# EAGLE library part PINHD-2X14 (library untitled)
PIN HEADER
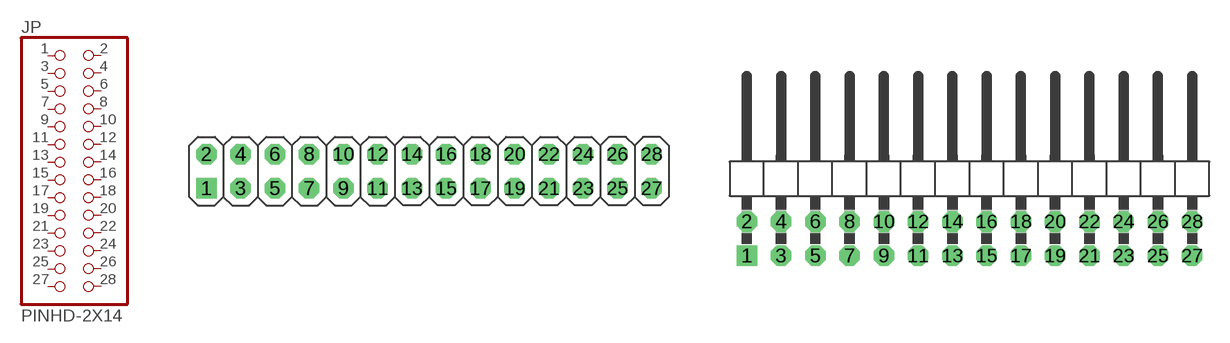
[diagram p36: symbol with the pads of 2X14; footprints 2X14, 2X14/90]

Designator prefix JP

## PINHD-2X14_2.54  [2X14]
1  1  pas
2  2  pas
3  3  pas
4  4  pas
5  5  pas
6  6  pas
7  7  pas
8  8  pas
9  9  pas
10  10  pas
11  11  pas
12  12  pas
13  13  pas
14  14  pas
15  15  pas
16  16  pas
17  17  pas
18  18  pas
19  19  pas
20  20  pas
21  21  pas
22  22  pas
23  23  pas
24  24  pas
25  25  pas
26  26  pas
27  27  pas
28  28  pas

## PINHD-2X14_2.54-90°  [2X14/90]
Pads as for 2X14

## PINHD-2X14_2.00  [2X14M]
Pads as for 2X14

## PINHD-2X14_2.54-SMD  [2X14SMD]
Pads as for 2X14

## PINHD-2X14_2.54-SMD-90°  [2X14SMD/90]
Pads as for 2X14

## Footprint 2X14 (pad centres in mm)
PIN HEADER - 2.54
drill 1.016 square: 1 -16.51,-1.27
drill 1.016 octagon: 2 -16.51,1.27; 3 -13.97,-1.27; 4 -13.97,1.27; 5 -11.43,-1.27; 6 -11.43,1.27; 7 -8.89,-1.27; 8 -8.89,1.27; 9 -6.35,-1.27; 10 -6.35,1.27; 11 -3.81,-1.27; 12 -3.81,1.27; 13 -1.27,-1.27; 14 -1.27,1.27; 15 1.27,-1.27; 16 1.27,1.27; 17 3.81,-1.27; 18 3.81,1.27; 19 6.35,-1.27; 20 6.35,1.27; 21 8.89,-1.27; 22 8.89,1.27; 23 11.43,-1.27; 24 11.43,1.27; 25 13.97,-1.27; 26 13.97,1.27; 27 16.51,-1.27; 28 16.51,1.27

## Footprint 2X14/90 (pad centres in mm)
PIN HEADER - 2.54 90°
drill 1.016 square: 1 -16.51,-6.35
drill 1.016 octagon: 2 -16.51,-3.81; 3 -13.97,-6.35; 4 -13.97,-3.81; 5 -11.43,-6.35; 6 -11.43,-3.81; 7 -8.89,-6.35; 8 -8.89,-3.81; 9 -6.35,-6.35; 10 -6.35,-3.81; 11 -3.81,-6.35; 12 -3.81,-3.81; 13 -1.27,-6.35; 14 -1.27,-3.81; 15 1.27,-6.35; 16 1.27,-3.81; 17 3.81,-6.35; 18 3.81,-3.81; 19 6.35,-6.35; 20 6.35,-3.81; 21 8.89,-6.35; 22 8.89,-3.81; 23 11.43,-6.35; 24 11.43,-3.81; 25 13.97,-6.35; 26 13.97,-3.81; 27 16.51,-6.35; 28 16.51,-3.81

## Footprint 2X14M (pad centres in mm)
PIN HEADER - 2
drill 0.914 square: 1 -13,-1
drill 0.914 round: 2 -13,1; 3 -11,-1; 4 -11,1; 5 -9,-1; 6 -9,1; 7 -7,-1; 8 -7,1; 9 -5,-1; 10 -5,1; 11 -3,-1; 12 -3,1; 13 -1,-1; 14 -1,1; 15 1,-1; 16 1,1; 17 3,-1; 18 3,1; 19 5,-1; 20 5,1; 21 7,-1; 22 7,1; 23 9,-1; 24 9,1; 25 11,-1; 26 11,1; 27 13,-1; 28 13,1

## Footprint 2X14SMD (pad centres in mm)
PIN HEADER - 2.54 SMD
smd 1.016 x 3.302: 1 -1.27,-3.81; 2 -1.27,1.27; 3 1.27,-3.81; 4 1.27,1.27; 5 3.81,-3.81; 6 3.81,1.27; 7 6.35,-3.81; 8 6.35,1.27; 9 8.89,-3.81; 10 8.89,1.27; 11 11.43,-3.81; 12 11.43,1.27; 13 13.97,-3.81; 14 13.97,1.27; 15 16.51,-3.81; 16 16.51,1.27; 17 19.05,-3.81; 18 19.05,1.27; 19 21.59,-3.81; 20 21.59,1.27; 21 24.13,-3.81; 22 24.13,1.27; 23 26.67,-3.81; 24 26.67,1.27; 25 29.21,-3.81; 26 29.21,1.27; 27 31.75,-3.81; 28 31.75,1.27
